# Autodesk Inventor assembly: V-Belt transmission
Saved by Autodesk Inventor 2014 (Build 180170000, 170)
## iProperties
Created: 2013-12
Part Number: V-Belt transmission
Document SubType Name: Assembly
Designer: Bram
ClientObjectVersion: 1
Author: Bram
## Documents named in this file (2)
- D:\gDrive\Google Drive\Hobby\3D Printer\3D printer\Inventor\PrinterAssambly\Design Accelerator\V-Belt transmission1.iam
- D:\gDrive\Google Drive\Hobby\3D Printer\3D printer\Inventor\PrinterAssambly\Design Accelerator\V-Belt1.ipt
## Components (1 placed, 1 different names)
1. V-Belt:1
